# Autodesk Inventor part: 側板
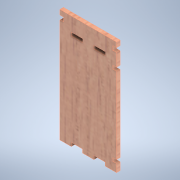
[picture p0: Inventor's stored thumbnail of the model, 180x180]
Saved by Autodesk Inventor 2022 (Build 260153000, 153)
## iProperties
Created: 2024-11
Part Number: 側板
Material: 木 (オーク)
Document SubType Name: Modeling
Designer: shimizu
Density: 0.76 g/cm^3
Appearance: ホワイト オーク材 - ナチュラル 標準の光沢
Author: shimizu
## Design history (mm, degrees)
sketch "スケッチ1"
  geometry: L1 (-20.243, 58.107)-(19.757, 58.107); L2 (-4.243, -21.893)-(-4.243, -19.393); L3 (-4.243, -19.393)-(-12.243, -19.393); L4 (-12.243, -19.393)-(-12.243, -21.893); L5 (11.757, -21.893)-(11.757, -19.393); L6 (11.757, -19.393)-(3.757, -19.393); L7 (3.757, -19.393)-(3.757, -21.893); L8 (-12.243, 48.107)-(-4.243, 48.107); L9 (-4.243, 48.107)-(-4.243, 45.607); L10 (-4.243, 45.607)-(-12.243, 45.607); L11 (-12.243, 45.607)-(-12.243, 48.107); L12 (3.757, 48.107)-(11.757, 48.107); L13 (11.757, 48.107)-(11.757, 45.607); L14 (11.757, 45.607)-(3.757, 45.607); L15 (3.757, 45.607)-(3.757, 48.107); L16 (-12.243, -21.893)-(-20.243, -21.893); L17 (19.757, -21.893)-(11.757, -21.893); L18 (3.757, -21.893)-(-4.243, -21.893); L19 (-20.243, 54.607)-(-17.743, 54.607); L20 (-17.743, 54.607)-(-17.743, 51.607); L21 (-17.743, 51.607)-(-20.243, 51.607); L22 (19.757, 54.607)-(17.257, 54.607); L23 (17.257, 54.607)-(17.257, 51.607); L24 (17.257, 51.607)-(19.757, 51.607); L25 (-20.243, -21.893)-(-20.243, 51.607); L26 (-20.243, 54.607)-(-20.243, 58.107); L27 (19.757, 58.107)-(19.757, 54.607); L28 (19.757, 51.607)-(19.757, -21.893); L29 (19.757, 42.607)-(17.257, 42.607); L30 (17.257, 42.607)-(17.257, 40.107); L31 (17.257, 40.107)-(19.757, 40.107); L32 (19.757, 40.107)-(19.757, 42.607); L33 (-20.243, -13.712)-(-17.743, -13.712); L34 (-17.743, -13.712)-(-17.743, -16.212); L35 (-17.743, -16.212)-(-20.243, -16.212); L36 (-20.243, -16.212)-(-20.243, -13.712); L37 (19.757, -13.893)-(17.257, -13.893); L38 (17.257, -13.893)-(17.257, -16.393); L39 (17.257, -16.393)-(19.757, -16.393); L40 (19.757, -16.393)-(19.757, -13.893); 4 further points
  constraints: 80 end point, 21 parallel, 9 perpendicular, 8 horizontal, 3 point on line, 2 collinear
  dimensions: "d27" = 80 distance between parallel lines of L17 L1; "d28" = 40 distance between parallel lines of L25 L28; "d29" = 3 distance between parallel lines of L29 L14; "d30" = 2.5 distance of L30.end L31.end; "d31" = 2.5 distance between parallel lines of L16 L3; "d32" = 3.181 distance between parallel lines of L3 L35; "d33" = 2.5 distance of L33.end L34.end; "d34" = 2.5 distance between parallel lines of L36 L34; "d35" = 2.5 distance between parallel lines of L29 L31; "d37" = 2.5 distance of L37.start L37.end; "d38" = 2.5 distance of L37.end L38.end; "d39" = 2.5 distance of L5.start L5.end; "d40" = 3 distance between parallel lines of L6 L39; "d41" = 3 distance between parallel lines of L24 L22; "d42" = 3.5 distance between parallel lines of L19 L1; "d43" = 3.5 distance between parallel lines of L22 L1; "d44" = 3 distance between parallel lines of L21 L19
extrude "押し出し1" new body sketch "スケッチ1" distance "d13" = 2.5; taper "d14" = 0 deg
node "ソリッド1"
